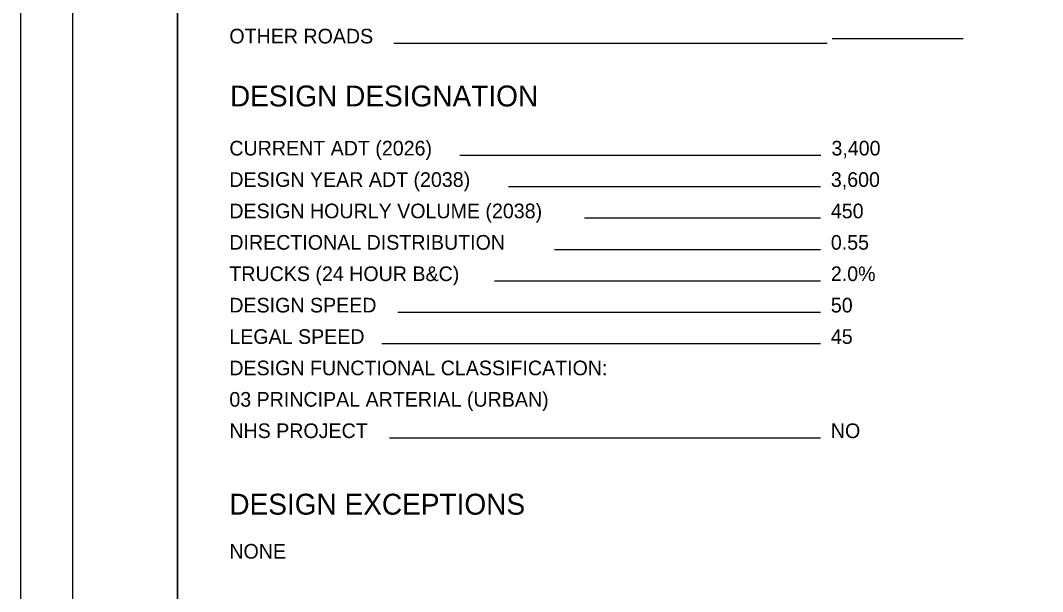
# Model space of a CAD drawing. Extents: x 0 to 34, y 0 to 22.
# Drawn here: x 0 to 9.76, y 5.64 to 11.09 of the extents above; entities that cross this region are included whole.
import ezdxf

# ---------------------------------------------------------------- set-up
doc = ezdxf.new("R2010")
doc.units = 0
for name, color, linetype in [('SH_Border', 7, 'Continuous'), ('SH_Cut_Line', 7, 'Continuous'), ('SH_Data', 7, 'Continuous'), ('SH_Text', 7, 'Continuous')]:
    doc.layers.add(name, color=color, linetype=linetype)

msp = doc.modelspace()

# ---------------------------------------------------------------- linework, layer by layer
at = {"layer": 'SH_Border'}
for points in [[(0.5, 21.498), (1.5, 21.498), (1.5, 0.498), (0.5, 0.498)], [(1.5, 21.498), (33.5, 21.498), (33.5, 0.498), (1.5, 0.498)]]:
    msp.add_lwpolyline(points, close=True, dxfattribs=at)
at = {"layer": 'SH_Cut_Line'}
msp.add_lwpolyline([(0, -0.002), (34, -0.002), (34, 21.998), (0, 21.998)], close=True, dxfattribs=at)
at = {"layer": 'SH_Data'}
for p, q in [((7.7, 10.8747), (3.5657, 10.8747)), ((9, 10.9203), (7.75, 10.9203)), ((7.6424, 9.8042), (4.1936, 9.8042)), ((7.6368, 9.5042), (4.6592, 9.5042)), ((7.6368, 9.2042), (5.3852, 9.2042)), ((7.6368, 8.9042), (5.0988, 8.9042)), ((7.6368, 8.6042), (4.5259, 8.6042)), ((7.6368, 8.3042), (3.6035, 8.3042)), ((7.6368, 8.0042), (3.4488, 8.0042)), ((7.6368, 7.1042), (3.5243, 7.1042))]:
    msp.add_line(p, q, dxfattribs=at)

# ---------------------------------------------------------------- texts
msp.add_text('DESIGN DESIGNATION', height=0.2, dxfattribs=at).set_placement((2, 10.2727))
at = {"layer": 'SH_Text'}
for s, height, p in [('OTHER ROADS', 0.14, (1.9944, 10.8747)), ('CURRENT ADT (2026)', 0.14, (1.9944, 9.8042)), ('3,400', 0.14, (7.7424, 9.8042)), ('DESIGN YEAR ADT (2038)', 0.14, (1.9944, 9.5042)), ('3,600', 0.14, (7.7368, 9.5042)), ('DESIGN HOURLY VOLUME (2038)', 0.14, (1.9944, 9.2042)), ('450', 0.14, (7.7368, 9.2042)), ('DIRECTIONAL DISTRIBUTION', 0.14, (1.9944, 8.9042)), ('0.55', 0.14, (7.7368, 8.9042)), ('TRUCKS (24 HOUR B&C)', 0.14, (1.9944, 8.6042)), ('2.0%', 0.14, (7.7368, 8.6042)), ('DESIGN SPEED', 0.14, (1.9944, 8.3042)), ('50', 0.14, (7.7368, 8.3042)), ('LEGAL SPEED', 0.14, (1.9944, 8.0042)), ('45', 0.14, (7.7368, 8.0042)), ('DESIGN FUNCTIONAL CLASSIFICATION:', 0.14, (1.9944, 7.7042)), ('03 PRINCIPAL ARTERIAL (URBAN)', 0.14, (1.9944, 7.4042)), ('NHS PROJECT', 0.14, (1.9944, 7.1042)), ('NO', 0.14, (7.7368, 7.1042)), ('DESIGN EXCEPTIONS', 0.2, (1.9944, 6.3724)), ('NONE', 0.14, (1.9944, 5.9524))]:
    msp.add_text(s, height=height, dxfattribs=at).set_placement(p)

doc.saveas('drawing.dxf')
